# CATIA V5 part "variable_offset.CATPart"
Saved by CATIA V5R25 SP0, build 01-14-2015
Part number: Part1
Bounding box of the stored display mesh (mm): x -40 to 40, y -142.035 to 125.092, z -43.841 to 47.521
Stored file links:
  E:\cadcim\GSD_cat_v5-6r2014\Part_files\variable_offset.CATPart
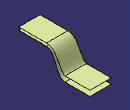
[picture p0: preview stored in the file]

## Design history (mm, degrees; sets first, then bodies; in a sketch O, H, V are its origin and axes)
Set1
  Sketch1 on yz-plane, origin (0, 0, 0), H (0, 1, 0), V (0, 0, 1)
    line L1 (-37.9526, 37.5213) -> (-142.0346, 37.5213)
    horizontal: L1 H
  Sketch2 on yz-plane, origin (0, 0, 0), H (0, 1, 0), V (0, 0, 1)
    line L1 (31.6324, -43.8406) -> (125.0922, -43.8406)
    horizontal: L1 H
  Extrude1: Lim1 40, Lim2 40, Element1 Sketch1
  Extrude2: Lim1 40, Lim2 40, Element1 Sketch2
  Blend1: StartLimit {blendlimit Curve edge of Extrude1, Support Extrude1}, EndLimit {blendlimit Curve edge of Extrude2, Support Extrude2}
  Join1: Elements (Extrude1; Blend1; Extrude2)
  GSOVariableOffset1: GlobalSurface Join1, ListOfConstraints Blend1
Body1 (main body)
